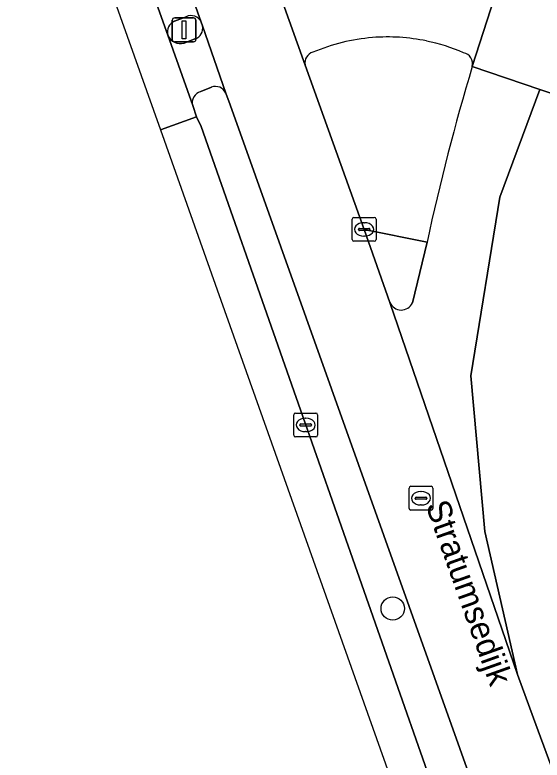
# Model space of a CAD drawing. Extents: x 161798 to 162385, y 382315 to 382833.
# Drawn here: x 161798.21 to 161820.29, y 382537.1 to 382568.31 of the extents above; entities that cross this region are included whole.
import ezdxf

# ---------------------------------------------------------------- set-up
doc = ezdxf.new("R2010")
doc.units = 0
for name, color, linetype in [('IMGEO_Berm_groen', 7, 'Continuous'), ('IMGEO_Boom', 7, 'Continuous'), ('IMGEO_Fietspad_open', 7, 'Continuous'), ('IMGEO_Kolk', 7, 'Continuous'), ('IMGEO_Openbare_ruimte_label', 7, 'Continuous'), ('IMGEO_OVBaan_gesloten', 7, 'Continuous'), ('IMGEO_Rijbaan_lokaal_gesloten', 7, 'Continuous'), ('IMGEO_Rioolput', 7, 'Continuous'), ('IMGEO_Verkeerseiland_groen', 7, 'Continuous'), ('IMGEO_Verkeerseiland_open', 7, 'Continuous'), ('IMGEO_Verkeersregelinstallatiepaal', 7, 'Continuous'), ('IMGEO_Voetpad_open', 7, 'Continuous')]:
    doc.layers.add(name, color=color, linetype=linetype)

msp = doc.modelspace()

# ---------------------------------------------------------------- linework, layer by layer
at = {"layer": 'IMGEO_Berm_groen'}
for points in [[(161806.435, 382565.275), (161805.991, 382565.093)], [(161839.819, 382472.947), (161833.175, 382491.839), (161830.261, 382500), (161816.839, 382537.592), (161807.218, 382564.539), (161807.037, 382565.026)], [(161805.654, 382564.508), (161805.816, 382564.034), (161806.006, 382563.637), (161816.518, 382533.648), (161822.311, 382517.164), (161822.731, 382516.012), (161828.156, 382500), (161833.649, 382483.027), (161839.128, 382465.362), (161844.598, 382447.699), (161849.721, 382431.019), (161855.195, 382413.368), (161855.242, 382413.135)]]:
    msp.add_lwpolyline(points, dxfattribs=at)
for centre, radius, start, end in [((161806.104, 382564.638), 0.469, 103.9736, 196.1367), ((161806.611, 382564.85), 0.461, 22.529, 112.529)]:
    msp.add_arc(centre, radius, start, end, dxfattribs=at)
at = {"layer": 'IMGEO_Boom'}
msp.add_circle((161814.031, 382543.451), 0.489, dxfattribs=at)
at = {"layer": 'IMGEO_Fietspad_open'}
for points in [[(161806.009, 382568.002), (161805.016, 382570.802)], [(161803.583, 382570.364), (161804.613, 382567.457)], [(161804.897, 382568.047), (161805.38, 382568.23)]]:
    msp.add_lwpolyline(points, dxfattribs=at)
for centre, radius, start, end in [((161805.585, 382567.814), 0.464, 23.9275, 116.2234), ((161805.095, 382567.588), 0.5, 113.39, 195.2018)]:
    msp.add_arc(centre, radius, start, end, dxfattribs=at)
at = {"layer": 'IMGEO_Kolk'}
for p, q in [((161812.335, 382558.901), (161812.335, 382559.753)), ((161812.41, 382559.827), (161813.262, 382559.827)), ((161813.336, 382559.753), (161813.336, 382558.901)), ((161812.823, 382559.607), (161812.848, 382559.607)), ((161812.594, 382559.321), (161812.594, 382559.333)), ((161813.032, 382559.284), (161812.634, 382559.284)), ((161812.637, 382559.37), (161813.035, 382559.37)), ((161813.078, 382559.333), (161813.078, 382559.321)), ((161813.262, 382558.827), (161812.41, 382558.827)), ((161812.846, 382559.047), (161812.821, 382559.047)), ((161809.961, 382551.637), (161810.813, 382551.637)), ((161809.886, 382550.711), (161809.886, 382551.563)), ((161810.374, 382551.417), (161810.399, 382551.417)), ((161810.887, 382551.563), (161810.887, 382550.711)), ((161810.145, 382551.131), (161810.145, 382551.143)), ((161810.583, 382551.094), (161810.185, 382551.094)), ((161810.188, 382551.18), (161810.586, 382551.18)), ((161810.629, 382551.143), (161810.629, 382551.131)), ((161810.397, 382550.857), (161810.372, 382550.857)), ((161810.813, 382550.637), (161809.961, 382550.637))]:
    msp.add_line(p, q, dxfattribs=at)
for points in [[(161812.335, 382558.901), (161812.335, 382559.753)], [(161812.41, 382559.827), (161813.262, 382559.827)], [(161813.336, 382559.753), (161813.336, 382558.901)], [(161813.262, 382558.827), (161812.41, 382558.827)], [(161809.961, 382551.637), (161810.813, 382551.637)], [(161809.886, 382550.711), (161809.886, 382551.563)], [(161810.887, 382551.563), (161810.887, 382550.711)], [(161810.813, 382550.637), (161809.961, 382550.637)]]:
    msp.add_lwpolyline(points, dxfattribs=at)
for centre, radius, start, end in [((161812.412, 382559.751), 0.0765, 91.552, 178.448), ((161812.412, 382559.751), 0.0765, 91.552, 178.448), ((161813.26, 382559.751), 0.0765, 1.552, 88.448), ((161813.26, 382559.751), 0.0765, 1.552, 88.448), ((161812.634, 382559.33), 0.0403, 85.8775, 175.7526), ((161812.631, 382559.32), 0.0366, 178.938, 274.7102), ((161813.035, 382559.327), 0.043, 264.8664, 352.4533), ((161813.039, 382559.332), 0.0386, 1.7309, 96.639), ((161812.412, 382558.903), 0.0765, 181.552, 268.448), ((161812.412, 382558.903), 0.0765, 181.552, 268.448), ((161813.26, 382558.903), 0.0765, 271.552, 358.448), ((161813.26, 382558.903), 0.0765, 271.552, 358.448), ((161809.963, 382551.561), 0.0765, 91.552, 178.448), ((161809.963, 382551.561), 0.0765, 91.552, 178.448), ((161810.811, 382551.561), 0.0765, 1.552, 88.448), ((161810.811, 382551.561), 0.0765, 1.552, 88.448), ((161810.185, 382551.14), 0.0403, 85.8775, 175.7526), ((161810.182, 382551.13), 0.0366, 178.938, 274.7102), ((161810.586, 382551.137), 0.043, 264.8664, 352.4533), ((161810.59, 382551.142), 0.0386, 1.7309, 96.639), ((161809.963, 382550.713), 0.0765, 181.552, 268.448), ((161809.963, 382550.713), 0.0765, 181.552, 268.448), ((161810.811, 382550.713), 0.0765, 271.552, 358.448), ((161810.811, 382550.713), 0.0765, 271.552, 358.448)]:
    msp.add_arc(centre, radius, start, end, dxfattribs=at)
for centre, major_axis, ratio, start_param, end_param in [((161812.822, 382559.327), (-0.387, 0.002), 0.722429, 4.712389, 7.853982), ((161812.847, 382559.327), (-0.39, 0.002), 0.717154, 1.570796, 4.712389), ((161810.373, 382551.137), (-0.387, 0.002), 0.722429, 4.712389, 7.853982), ((161810.398, 382551.137), (-0.39, 0.002), 0.717154, 1.570796, 4.712389)]:
    msp.add_ellipse(centre, major_axis=major_axis, ratio=ratio, start_param=start_param, end_param=end_param, dxfattribs=at)
at = {"layer": 'IMGEO_OVBaan_gesloten'}
msp.add_lwpolyline([(161855.242, 382413.135), (161855.195, 382413.368), (161849.721, 382431.019), (161844.598, 382447.699), (161839.128, 382465.362), (161833.649, 382483.027), (161828.156, 382500), (161822.731, 382516.012), (161822.311, 382517.164), (161816.518, 382533.648), (161806.006, 382563.637), (161805.816, 382564.034), (161804.299, 382563.495), (161806.831, 382556.367), (161829.727, 382491.906), (161840.102, 382457.985), (161861.946, 382386.568), (161872.677, 382345.565)], dxfattribs=at)
at = {"layer": 'IMGEO_Rijbaan_lokaal_gesloten'}
for points in [[(161798.207, 382580.647), (161804.299, 382563.495), (161805.816, 382564.034), (161805.654, 382564.508), (161804.613, 382567.457), (161803.583, 382570.364), (161803.175, 382571.525), (161800.766, 382578.342)], [(161813.918, 382556.26), (161812.835, 382559.326), (161810.369, 382566.205), (161809.366, 382569.024), (161809.327, 382569.134), (161808.317, 382571.965), (161807.946, 382573.181), (161806.802, 382576.198), (161805.64, 382579.533), (161802.139, 382578.882), (161805.016, 382570.802), (161806.009, 382568.002), (161806.062, 382567.851), (161807.037, 382565.026), (161807.218, 382564.539), (161816.839, 382537.592), (161830.261, 382500), (161833.175, 382491.839), (161839.819, 382472.947)], [(161819.952, 382573.975), (161819.91, 382573.851), (161818.3, 382569.047), (161817.364, 382566.144), (161820.188, 382565.188), (161823.011, 382564.232), (161823.931, 382567.036), (161823.965, 382567.14), (161825.67, 382572.082)], [(161820.188, 382565.188), (161817.364, 382566.144)], [(161813.918, 382556.26), (161813.926, 382556.227), (161819.264, 382540.686), (161817.891, 382546.682), (161817.298, 382553.19), (161818.515, 382560.675), (161820.188, 382565.188)], [(161822.599, 382562.893), (161823.011, 382564.232), (161820.188, 382565.188), (161818.515, 382560.675), (161817.298, 382553.19), (161817.891, 382546.682), (161819.264, 382540.686), (161819.934, 382538.863), (161823.261, 382529.817), (161833.869, 382499.799), (161843.36, 382471.44), (161860.968, 382415.409)], [(161815.469, 382558.795), (161814.854, 382556.248)], [(161849.061, 382444.311), (161852.924, 382431.895), (161861.036, 382405.087), (161861.939, 382402.187), (161862.518, 382400.247), (161865.969, 382388.685), (161870.99, 382371.86), (161878.312, 382347.2), (161880.89, 382348.212), (161873.956, 382371.495), (161860.968, 382415.409), (161843.36, 382471.44), (161833.869, 382499.799), (161823.261, 382529.817), (161819.934, 382538.863), (161819.264, 382540.686), (161813.926, 382556.227), (161813.918, 382556.26)]]:
    msp.add_lwpolyline(points, dxfattribs=at)
for centre, radius, start, end in [((161909.558, 382538.452), 96.263, 163.28159, 167.79999), ((161814.389, 382556.464), 0.513, 203.4243, 335.1067)]:
    msp.add_arc(centre, radius, start, end, dxfattribs=at)
at = {"layer": 'IMGEO_Rioolput'}
for p, q in [((161814.716, 382547.643), (161814.716, 382548.495)), ((161814.791, 382548.569), (161815.643, 382548.569)), ((161815.717, 382548.495), (161815.717, 382547.643)), ((161815.204, 382548.349), (161815.229, 382548.349)), ((161814.975, 382548.063), (161814.975, 382548.075)), ((161815.413, 382548.026), (161815.015, 382548.026)), ((161815.018, 382548.112), (161815.416, 382548.112)), ((161815.459, 382548.075), (161815.459, 382548.063)), ((161815.643, 382547.569), (161814.791, 382547.569)), ((161815.227, 382547.789), (161815.202, 382547.789))]:
    msp.add_line(p, q, dxfattribs=at)
for points in [[(161814.716, 382547.643), (161814.716, 382548.495)], [(161814.791, 382548.569), (161815.643, 382548.569)], [(161815.717, 382548.495), (161815.717, 382547.643)], [(161815.643, 382547.569), (161814.791, 382547.569)]]:
    msp.add_lwpolyline(points, dxfattribs=at)
for centre, radius, start, end in [((161814.793, 382548.493), 0.0765, 91.552, 178.448), ((161814.793, 382548.493), 0.0765, 91.552, 178.448), ((161815.641, 382548.493), 0.0765, 1.552, 88.448), ((161815.641, 382548.493), 0.0765, 1.552, 88.448), ((161815.015, 382548.072), 0.0403, 85.8775, 175.7526), ((161815.012, 382548.062), 0.0366, 178.938, 274.7102), ((161815.416, 382548.069), 0.043, 264.8664, 352.4533), ((161815.42, 382548.074), 0.0386, 1.7309, 96.639), ((161814.793, 382547.645), 0.0765, 181.552, 268.448), ((161814.793, 382547.645), 0.0765, 181.552, 268.448), ((161815.641, 382547.645), 0.0765, 271.552, 358.448), ((161815.641, 382547.645), 0.0765, 271.552, 358.448)]:
    msp.add_arc(centre, radius, start, end, dxfattribs=at)
for centre, major_axis, ratio, start_param, end_param in [((161815.203, 382548.069), (-0.387, 0.002), 0.722429, 4.712389, 7.853982), ((161815.228, 382548.069), (-0.39, 0.002), 0.717154, 1.570796, 4.712389)]:
    msp.add_ellipse(centre, major_axis=major_axis, ratio=ratio, start_param=start_param, end_param=end_param, dxfattribs=at)
at = {"layer": 'IMGEO_Verkeerseiland_groen'}
msp.add_lwpolyline([(161810.369, 382566.205), (161812.835, 382559.326), (161815.469, 382558.795)], dxfattribs=at)
for centre, radius, start, end in [((161813.815, 382559.441), 7.942, 94.5462, 113.1584), ((161813.816, 382559.44), 7.944, 78.1572, 94.5545), ((161813.825, 382559.452), 7.929, 66.3942, 78.2021), ((161810.808, 382566.308), 0.451, 105.0213, 193.1766), ((161816.918, 382566.264), 0.462, 344.9606, 79.8007), ((161909.558, 382538.452), 96.263, 163.28159, 167.79999)]:
    msp.add_arc(centre, radius, start, end, dxfattribs=at)
at = {"layer": 'IMGEO_Verkeerseiland_open'}
for points in [[(161805.38, 382568.23), (161804.897, 382568.047)], [(161806.062, 382567.851), (161806.009, 382568.002)], [(161805.292, 382567.128), (161805.75, 382567.299)], [(161814.854, 382556.248), (161815.469, 382558.795), (161812.835, 382559.326), (161813.918, 382556.26)]]:
    msp.add_lwpolyline(points, dxfattribs=at)
for centre, radius, start, end in [((161805.585, 382567.814), 0.464, 23.9275, 116.2234), ((161805.095, 382567.588), 0.5, 113.39, 195.2018), ((161805.612, 382567.741), 0.463, 287.363, 13.6852), ((161805.135, 382567.668), 0.563, 202.0648, 286.2315), ((161814.389, 382556.464), 0.513, 203.4243, 335.1067)]:
    msp.add_arc(centre, radius, start, end, dxfattribs=at)
at = {"layer": 'IMGEO_Verkeersregelinstallatiepaal'}
for p, q in [((161804.899, 382568.181), (161805.689, 382568.181)), ((161805.689, 382568.181), (161804.899, 382568.181)), ((161804.799, 382567.281), (161804.799, 382568.081)), ((161804.799, 382568.081), (161804.799, 382567.281)), ((161805.789, 382568.081), (161805.789, 382567.281)), ((161805.789, 382567.281), (161805.789, 382568.081)), ((161805.689, 382567.181), (161804.899, 382567.181)), ((161804.899, 382567.181), (161805.689, 382567.181))]:
    msp.add_line(p, q, dxfattribs=at)
msp.add_lwpolyline([(161805.219, 382568.056), (161805.369, 382568.056), (161805.369, 382567.306), (161805.219, 382567.306), (161805.219, 382568.056)], dxfattribs=at)
for centre, start, end in [((161804.899, 382568.081), 90, 180), ((161804.899, 382568.081), 90, 180), ((161805.689, 382568.081), 0, 90), ((161805.689, 382568.081), 360, 90), ((161804.899, 382567.281), 180, 270), ((161804.899, 382567.281), 180, 270), ((161805.689, 382567.281), 270, 0), ((161805.689, 382567.281), 270, 0)]:
    msp.add_arc(centre, 0.1, start, end, dxfattribs=at)
at = {"layer": 'IMGEO_Voetpad_open'}
for points in [[(161809.366, 382569.024), (161810.369, 382566.205)], [(161817.364, 382566.144), (161818.3, 382569.047)], [(161807.037, 382565.026), (161806.062, 382567.851)], [(161804.613, 382567.457), (161805.654, 382564.508)], [(161805.75, 382567.299), (161805.292, 382567.128)], [(161805.991, 382565.093), (161806.435, 382565.275)]]:
    msp.add_lwpolyline(points, dxfattribs=at)
for centre, radius, start, end in [((161805.612, 382567.741), 0.463, 287.363, 13.6852), ((161805.135, 382567.668), 0.563, 202.0648, 286.2315), ((161813.815, 382559.441), 7.942, 94.5462, 113.1584), ((161813.816, 382559.44), 7.944, 78.1572, 94.5545), ((161813.825, 382559.452), 7.929, 66.3942, 78.2021), ((161810.808, 382566.308), 0.451, 105.0213, 193.1766), ((161816.918, 382566.264), 0.462, 344.9606, 79.8007), ((161806.104, 382564.638), 0.469, 103.9736, 196.1367), ((161806.611, 382564.85), 0.461, 22.529, 112.529)]:
    msp.add_arc(centre, radius, start, end, dxfattribs=at)

# ---------------------------------------------------------------- texts
at = {"layer": 'IMGEO_Openbare_ruimte_label'}
msp.add_text('Stratumsedijk', height=1, rotation=289.6307, dxfattribs=at).set_placement((161815.403, 382547.773))

doc.saveas('drawing.dxf')
